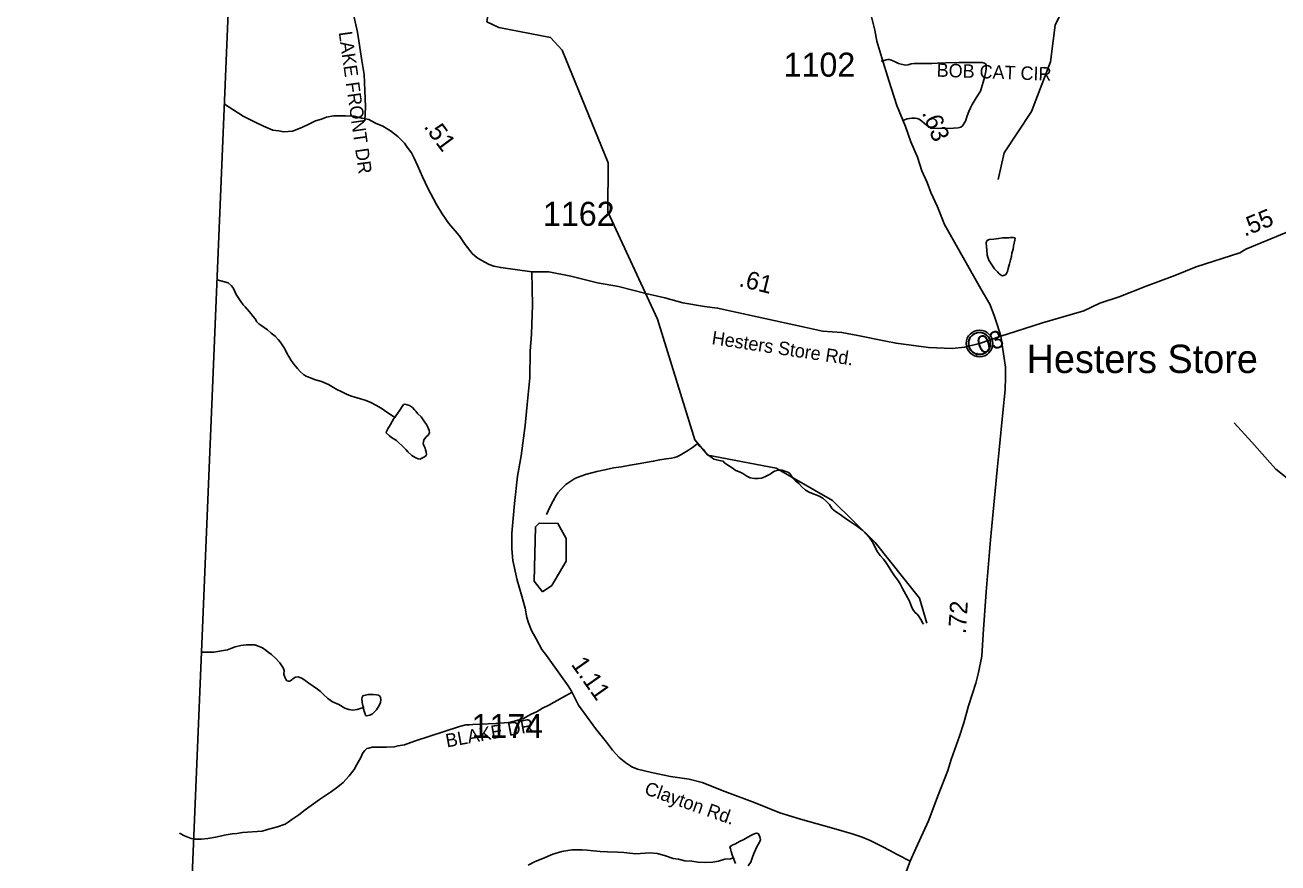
# Model space of a CAD drawing. Extents: x 1950930 to 2061844, y 904556 to 1017002.
# Drawn here: x 1954667 to 1963523, y 935352 to 941273 of the extents above; entities that cross this region are included whole.
import ezdxf

# ---------------------------------------------------------------- set-up
doc = ezdxf.new("R2010")
doc.units = 0
for name, color, linetype in [('Exist Boundary Political CountyLine', 7, 'Continuous'), ('Exist Civil Demographics Community CELL', 7, 'Continuous'), ('Exist Civil Demographics Community Label', 7, 'Continuous'), ('Exist Hydrographic Creek Single Shore', 7, 'Continuous'), ('Exist Hydrographic Misc Water Feature', 7, 'Continuous'), ('Exist Road Non-System Type 51', 7, 'Continuous'), ('Exist Road Non-System Type 51 Label', 7, 'Continuous'), ('Exist Road Primary US Structure Standard Bridge CELL', 7, 'Continuous'), ('Exist Road Secondary Type 41 Attributed', 7, 'Continuous'), ('Exist Road Secondary Type 51 Attributed', 7, 'Continuous'), ('Exist Road Secondary Type 51 Label', 7, 'Continuous'), ('Exist Road Secondary Type 51 Number Label', 7, 'Continuous')]:
    doc.layers.add(name, color=color, linetype=linetype)

msp = doc.modelspace()

# ---------------------------------------------------------------- linework, layer by layer
at = {"layer": 'Exist Boundary Political CountyLine'}
msp.add_lwpolyline([(1954666.9, 907077.7), (1956979.8, 962278.8), (1958720.5, 998184), (1959482.1, 1016167.2)], dxfattribs=at)
at = {"layer": 'Exist Civil Demographics Community CELL'}
msp.add_lwpolyline([(1961336.4, 939035.5), (1961337.4, 939041.1), (1961339.1, 939047.7), (1961342, 939054.9), (1961345, 939060.6), (1961348.3, 939066.4), (1961352.1, 939071.5), (1961356, 939075.9), (1961360.6, 939080.5), (1961366.2, 939085.1), (1961371.6, 939088.7), (1961376.5, 939091.6), (1961381.5, 939094), (1961387, 939096.3), (1961392.6, 939098.2), (1961396.9, 939099.3), (1961401.8, 939100), (1961405.9, 939100.8), (1961412.3, 939101), (1961416.7, 939100.9), (1961422.4, 939100.7), (1961427.3, 939099.9), (1961432.2, 939098.9), (1961437.2, 939097.5), (1961442.4, 939095.6), (1961449, 939092.7), (1961455.3, 939089.2), (1961460.3, 939085.6), (1961465.5, 939081.6), (1961468.8, 939078.5), (1961472.9, 939074.1), (1961476.8, 939069.4), (1961479.9, 939064.8), (1961483, 939059.8), (1961485.5, 939054.6), (1961487.5, 939049.6), (1961489.1, 939044.6), (1961490.3, 939040), (1961491.4, 939034), (1961492.1, 939029.3), (1961492.3, 939023.3), (1961492.1, 939017.5), (1961491.6, 939011.8), (1961490.6, 939006.3), (1961489, 939000.2), (1961487.1, 938994.3), (1961484.8, 938989.3), (1961481.7, 938983.3), (1961478.4, 938977.9), (1961474.9, 938973.2), (1961470.7, 938968.5), (1961465.4, 938963.5), (1961460.4, 938959.4), (1961455.4, 938956), (1961451.1, 938953.5), (1961444.2, 938950.2), (1961437.1, 938947.5), (1961431.1, 938946.1), (1961424.5, 938944.8), (1961420.1, 938944.3), (1961415.6, 938944), (1961410, 938944), (1961405.8, 938944.4), (1961400.1, 938945.2), (1961394.2, 938946.5), (1961389.6, 938947.8), (1961384.4, 938949.7), (1961379.9, 938951.6), (1961375.9, 938953.9), (1961369.1, 938958), (1961363.5, 938962.2), (1961358.6, 938966.7), (1961354.2, 938971.6), (1961351, 938975.5), (1961348, 938979.7), (1961343.9, 938986.8), (1961342.2, 938990.4), (1961340.5, 938994.4), (1961337.9, 939002.6), (1961336.4, 939009.6), (1961335.7, 939014.8), (1961335.3, 939021.1), (1961335.3, 939025.8), (1961335.8, 939032.3)], close=True, dxfattribs=at)
for centre, radius in [((1961414, 939023.1), 94.3), ((1961413.7, 939023.4), 76.7)]:
    msp.add_circle(centre, radius, dxfattribs=at)
at = {"layer": 'Exist Hydrographic Creek Single Shore'}
for points in [[(1961546.5, 940181), (1961588.4, 940370.4), (1961780.5, 940661.9), (1961915.4, 941013.6), (1961949.5, 941272.2), (1962049.5, 941480.2), (1962058.3, 941647.3), (1962000.5, 941855.4), (1962033.5, 941953.2), (1961933.5, 942063.5), (1962068.4, 942937), (1962052.4, 943019.4), (1962086.4, 943337), (1962295.4, 943628.1), (1962528.5, 943787.4), (1962595.4, 943861.6), (1962612.4, 943969.5), (1962871.4, 944134.8), (1963046.5, 944101.7), (1963260.4, 944136.7), (1963552.4, 944393.2), (1963820.4, 944465.4)], [(1961040.5, 937047.1), (1960990.4, 937222.2), (1960675.5, 937616), (1960375.5, 937914.3), (1959975.4, 938142.4), (1959492.5, 938234.4), (1959401.5, 938341.3), (1959136.3, 939193.6), (1958787.3, 939952.4), (1958788.4, 940300.3), (1958464.4, 941094.6), (1958381.3, 941185), (1958015.3, 941254.9), (1957931.4, 941296), (1957948.5, 941404), (1958082.4, 941713), (1957949.5, 942103), (1957883.5, 942110.9), (1957574.4, 941963.1), (1957474.4, 941971.7)], [(1958353, 937814.4), (1958377, 937866.4), (1958401, 937910.4), (1958421.1, 937948.3), (1958433.2, 937968.3), (1958451.2, 937988.3), (1958489.4, 938026.2), (1958531.4, 938054.1), (1958553.3, 938068.1), (1958575.5, 938078.1), (1958629.4, 938096), (1958673.5, 938107.9), (1958709.6, 938117.8), (1958765.6, 938129.7), (1958825.6, 938143.6), (1958883.5, 938151.5), (1958943.5, 938163.3), (1958999.7, 938173.3), (1959065.8, 938183.1), (1959107.6, 938191), (1959153.7, 938200.9), (1959197.6, 938208.8), (1959235.7, 938212.8), (1959257.9, 938216.8), (1959273.9, 938222.8), (1959297.9, 938234.7), (1959355.9, 938268.6), (1959384, 938288.6), (1959416, 938310.5), (1959424, 938314.5)]]:
    msp.add_lwpolyline(points, dxfattribs=at)
at = {"layer": 'Exist Hydrographic Misc Water Feature'}
for points in [[(1961551, 939764.6), (1961577, 939768.5), (1961597.1, 939768.5), (1961621.1, 939770.4), (1961633, 939772.5), (1961651.1, 939772.4), (1961661.1, 939770.4), (1961665, 939766.4), (1961662.9, 939752.4), (1961655, 939710.4), (1961650.9, 939690.3), (1961642.9, 939660.4), (1961638.8, 939638.4), (1961632.6, 939614.4), (1961630.8, 939604.4), (1961626.7, 939586.5), (1961616.6, 939552.4), (1961610.7, 939532.4), (1961604.5, 939518.4), (1961596.5, 939508.5), (1961590.6, 939504.5), (1961582.4, 939502.5), (1961574.6, 939500.5), (1961552.6, 939514.6), (1961540.5, 939528.6), (1961520.6, 939550.6), (1961500.8, 939578.6), (1961478.6, 939612.7), (1961466.7, 939646.8), (1961464.9, 939684.8), (1961463, 939706.7), (1961461, 939736.8), (1961466.9, 939750.7), (1961480.9, 939758.7), (1961514.9, 939760.7), (1961547.1, 939764.6), (1961551, 939764.6)], [(1956024.2, 939472), (1956101.7, 939450.9), (1956125.7, 939430.9), (1956139.7, 939411), (1956159.6, 939368.8), (1956167.6, 939354.9), (1956191.5, 939318.9), (1956209.4, 939294.8), (1956223.3, 939280.7), (1956253.5, 939246.7), (1956279.3, 939214.6), (1956293.2, 939196.6), (1956305.3, 939176.6), (1956319.3, 939160.5), (1956333.2, 939152.5), (1956381.2, 939118.4), (1956407.3, 939096.4), (1956434.9, 939074.3), (1956457.1, 939050.3), (1956471, 939034.3), (1956489.1, 939006.2), (1956502.8, 938984.1), (1956518.8, 938950.2), (1956530.7, 938930.1), (1956548.7, 938902.1), (1956562.7, 938884.1), (1956576.6, 938866), (1956592.6, 938845.9), (1956610.7, 938824), (1956636.5, 938801.9), (1956654.6, 938791.8), (1956690.4, 938777.8), (1956720.6, 938765.8), (1956762.6, 938753.7), (1956812.4, 938733.6), (1956836.4, 938719.4), (1956870.5, 938697.4), (1956902.5, 938683.3), (1956938.3, 938665.3), (1956966.2, 938653.2), (1956998.2, 938643.2), (1957038.2, 938631), (1957070.2, 938623), (1957110.4, 938606.9), (1957146.1, 938586.8), (1957184.2, 938564.8), (1957230.1, 938532.7), (1957272, 938506.6), (1957280, 938500.6)], [(1957280, 938500.6), (1957288, 938510.6), (1957300.3, 938528.6), (1957316.3, 938552.5), (1957332.2, 938578.5), (1957342.3, 938592.5), (1957352.3, 938594.4), (1957368.3, 938590.4), (1957384.3, 938584.4), (1957406.1, 938570.4), (1957420.2, 938554.3), (1957430.3, 938544.3), (1957444.2, 938526.3), (1957465.9, 938504.3), (1957490.1, 938470.2), (1957504.1, 938450.2), (1957513.9, 938432.1), (1957524, 938408.1), (1957525.8, 938394.1), (1957517.8, 938376.2), (1957499.8, 938360.2), (1957491.8, 938350.2), (1957487.9, 938346.2), (1957483.8, 938330.2), (1957481.7, 938316.2), (1957485.6, 938302.2), (1957495.7, 938282.1), (1957497.7, 938272.2), (1957501.6, 938258.2), (1957503.7, 938240.1), (1957501.6, 938230.2), (1957489.5, 938222.2), (1957471.5, 938212.2), (1957459.6, 938206.2), (1957445.6, 938208.2), (1957425.5, 938216.3), (1957401.6, 938232.3), (1957373.7, 938256.4), (1957357.7, 938274.3), (1957331.6, 938298.5), (1957307.8, 938322.5), (1957291.9, 938336.6), (1957279.8, 938344.6), (1957257.8, 938358.6), (1957243.9, 938370.6), (1957219.9, 938390.7), (1957221.9, 938400.7), (1957232, 938418.7), (1957249.8, 938450.7), (1957274, 938492.6), (1957280, 938500.6)], [(1963213.3, 938462.2), (1963338.4, 938326.5), (1963450.5, 938200.6), (1963508.1, 938135.6), (1963612.1, 938053.1)], [(1959424, 938314.5), (1959424, 938310.5), (1959432, 938300.4), (1959445.9, 938290.4), (1959461.9, 938274.3), (1959477.7, 938252.4), (1959499.9, 938232.3), (1959523.8, 938214.3), (1959535.7, 938206.3), (1959555.8, 938200.2), (1959585.8, 938194.2), (1959601.8, 938190.1), (1959611.6, 938180.1), (1959633.8, 938164), (1959657.7, 938148), (1959691.8, 938125.9), (1959721.5, 938113.9), (1959741.6, 938103.8), (1959769.5, 938085.7), (1959793.5, 938073.7), (1959823.6, 938067.7), (1959849.5, 938067.7), (1959873.5, 938071.6), (1959895.6, 938079.6), (1959919.6, 938091.4), (1959933.5, 938099.4), (1959951.6, 938113.4), (1959963.7, 938119.4), (1959991.8, 938127.3), (1960017.6, 938127.3), (1960037.7, 938121.3), (1960051.6, 938115.2), (1960063.7, 938111.2), (1960071.7, 938105.2), (1960081.6, 938091.1), (1960093.5, 938071.1), (1960111.5, 938055.1), (1960137.4, 938033.1), (1960157.5, 938011), (1960183.5, 937987), (1960213.4, 937970.9), (1960245.4, 937958.9), (1960279.3, 937942.8), (1960305.3, 937928.7), (1960335.2, 937904.6), (1960353.3, 937884.6), (1960371.1, 937854.5), (1960395.1, 937836.6), (1960421.2, 937818.5), (1960463, 937788.5), (1960495, 937768.3), (1960551, 937730.2), (1960588.9, 937700.2), (1960610.8, 937678.2), (1960638.7, 937648), (1960654.9, 937624), (1960670.7, 937594), (1960690.6, 937553.9), (1960712.5, 937524), (1960734.5, 937499.9), (1960754.4, 937473.8), (1960774.5, 937439.7), (1960788.4, 937415.7), (1960808.3, 937387.7), (1960820.4, 937371.7), (1960836.2, 937349.6), (1960852.2, 937323.6), (1960870.2, 937291.5), (1960894, 937249.5), (1960918, 937201.4), (1960928, 937175.4), (1960937.9, 937153.4), (1960945.9, 937135.4), (1960957.8, 937121.3), (1960973.8, 937109.3), (1960981.8, 937097.2), (1960997.8, 937071.3), (1961005.8, 937061.3), (1961011.7, 937049.3), (1961017.6, 937039.2)], [(1958324.3, 937267.3), (1958390.4, 937311.8), (1958491.5, 937483.8), (1958491.5, 937644.5), (1958433.4, 937750.9), (1958300.3, 937753.6), (1958275.3, 937727.8), (1958265.5, 937344), (1958324.3, 937267.3)], [(1957058.1, 936450.7), (1957042.1, 936444.8), (1957014, 936436.9), (1956984.1, 936432.9), (1956956, 936437), (1956928.1, 936447), (1956884.2, 936471.1), (1956840.1, 936491.1), (1956806.1, 936515.2), (1956774.3, 936545.4), (1956756.3, 936563.3), (1956734.3, 936579.4), (1956702.3, 936601.4), (1956672.4, 936623.5), (1956646.3, 936641.6), (1956622.4, 936657.6), (1956608.4, 936663.7), (1956596.3, 936667.7), (1956578.5, 936665.7), (1956560.4, 936653.7), (1956552.4, 936645.7), (1956544.4, 936639.8), (1956536.4, 936637.7), (1956526.4, 936637.7), (1956518.4, 936639.8), (1956510.4, 936649.8), (1956502.4, 936663.9), (1956496.5, 936685.8), (1956498.5, 936711.9), (1956490.5, 936731.8), (1956466.7, 936766), (1956438.6, 936795.9), (1956408.7, 936824), (1956384.7, 936842.1), (1956370.8, 936854.2), (1956344.7, 936872.2), (1956322.8, 936882.3), (1956291, 936892.3), (1956259, 936894.3), (1956230.9, 936892.4), (1956192.8, 936888.5), (1956152.8, 936878.6), (1956120.8, 936866.6), (1956098.9, 936858.7), (1956001, 936840.9), (1955914, 936840.9)], [(1957058.1, 936450.7), (1957060.1, 936440.8), (1957066.1, 936418.7), (1957072, 936406.7), (1957074.1, 936394.7), (1957081.9, 936390.7), (1957104, 936396.7), (1957122.1, 936406.6), (1957152, 936434.6), (1957170.3, 936464.6), (1957180.1, 936486.5), (1957182.2, 936506.5), (1957180.3, 936520.5), (1957178.3, 936524.5), (1957172.3, 936532.5), (1957166.4, 936536.6), (1957150.4, 936540.6), (1957128.2, 936542.7), (1957116.3, 936542.7), (1957094.4, 936542.7), (1957062.2, 936534.8), (1957052.4, 936530.8), (1957048.3, 936510.8), (1957050.1, 936486.8), (1957054.2, 936464.8), (1957058.1, 936450.7)], [(1959674.4, 935387.6), (1959668.4, 935403.6), (1959658.4, 935433.7), (1959652.4, 935451.6), (1959648.5, 935465.6), (1959664.5, 935477.5), (1959688.5, 935487.6), (1959716.6, 935503.5), (1959742.6, 935515.5), (1959764.8, 935527.4), (1959792.7, 935543.4), (1959810.7, 935553.3), (1959828.8, 935561.3), (1959838.6, 935563.3), (1959850.7, 935557.3), (1959860.7, 935537.2), (1959864.6, 935515.3), (1959856.6, 935495.2), (1959842.5, 935471.3), (1959830.4, 935445.2), (1959820.4, 935423.3), (1959810.3, 935399.3), (1959802.3, 935371.3), (1959800.3, 935367.3), (1959798.4, 935361.4), (1959778.1, 935331.4)], [(1959674.4, 935387.6), (1959654.3, 935381.7), (1959614.3, 935379.7), (1959568.3, 935365.8), (1959528.2, 935357.9), (1959470.1, 935355.9), (1959424.2, 935358.1), (1959380.3, 935364.1), (1959330.3, 935368.2), (1959286.4, 935378.3), (1959248.3, 935384.3), (1959194.3, 935402.5), (1959138.3, 935418.7), (1959082.4, 935424.7), (1958984.4, 935416.8), (1958900.3, 935427.1), (1958858.2, 935429.1), (1958784.2, 935431.3), (1958732.3, 935433.4), (1958686.2, 935437.6), (1958640.3, 935443.6), (1958604.4, 935445.7), (1958576.3, 935445.7), (1958532.2, 935443.8), (1958462.3, 935431.9), (1958398.1, 935414.1), (1958326.1, 935384.2), (1958272.2, 935362.3), (1958224, 935336.4)], [(1959688.3, 935347.5), (1959680.3, 935371.6), (1959674.4, 935387.6)]]:
    msp.add_lwpolyline(points, dxfattribs=at)
at = {"layer": 'Exist Road Non-System Type 51'}
for points in [[(1957067.5, 940596.1), (1957072.6, 940694.9), (1957069.8, 940809.6), (1957062.9, 940923.4), (1957048.5, 941023), (1957017, 941222), (1956966, 941452.5), (1956921.5, 941690.8), (1956884.8, 941893.8), (1956867.8, 941933.1), (1956831.1, 941986.8), (1956782.6, 942041.8), (1956697.5, 942136.1), (1956692.2, 942168.8), (1956692.2, 942217.2), (1956689.4, 942240.3)], [(1960719.4, 941017.1), (1960739.1, 941022.8), (1960754.9, 941028.1), (1960767.1, 941030.6), (1960776, 941028.7), (1960792.6, 941023.7), (1960822.2, 941010.4), (1960841.1, 941001.3), (1960858.8, 940996.6), (1960891.1, 940988.4), (1960909.4, 940991.3), (1960931, 940999.2), (1960951.1, 941001.7), (1960973.4, 941002.2), (1961009.8, 941001.2), (1961075.6, 941001.2), (1961114.5, 941003.6), (1961176, 941005.6), (1961267, 941007.6), (1961349.1, 941007.6), (1961372.8, 941008.1), (1961409.1, 941008.1), (1961433.2, 941007.1), (1961448.5, 941004.1), (1961455.9, 940999.2), (1961461.2, 940990.9), (1961461.8, 940981), (1961461.8, 940966.2), (1961457.4, 940944.1), (1961448, 940902.3), (1961439.1, 940869.8), (1961432.8, 940844.8), (1961421.5, 940805.4), (1961391, 940759.6), (1961361.5, 940711.4), (1961350.1, 940687.3), (1961338.8, 940661.2), (1961326, 940630.8), (1961313.8, 940594.9), (1961294.5, 940559.9), (1961281.2, 940551.6), (1961261.6, 940546.2), (1961229.6, 940544.7), (1961123.4, 940542.7), (1961086.5, 940543.2), (1961070.2, 940545.2), (1961052, 940555), (1961038.8, 940565.3), (1961005.8, 940594.9), (1960988.1, 940608.6), (1960973.8, 940613.6), (1960958.5, 940615.5), (1960935.9, 940615.5), (1960903, 940609.6), (1960867.2, 940596.1)], [(1958534.6, 936558.8), (1958466.2, 936521.7), (1958368.8, 936467.5), (1958324.2, 936445.8), (1958286.9, 936421.8), (1958239.9, 936401.3), (1958190.5, 936373.6), (1958143.6, 936359.1), (1958118.2, 936350.7), (1958084.6, 936344.7), (1958054.5, 936341.1), (1957994.2, 936337.4), (1957831.8, 936330.9), (1957808.9, 936328.4), (1957783.5, 936327.2), (1957737.8, 936316.4), (1957419.9, 936212.8), (1957350, 936186.9), (1957304.2, 936179.8), (1957276.6, 936172.5), (1957222.4, 936171.3), (1957155, 936170.1), (1957121.2, 936169.5), (1957097.1, 936163.4), (1957082.8, 936159.9), (1957068.2, 936146.6), (1957055, 936130.9), (1957039.4, 936097.2), (1957011.6, 936047.9), (1956992.4, 936011.8), (1956957.5, 935967.2), (1956934.6, 935941.9), (1956916.5, 935921.4), (1956878, 935890.1), (1956832.2, 935856.4), (1956749.1, 935800.4), (1956648, 935728.2), (1956601, 935692.1), (1956551.8, 935658.3), (1956527.6, 935641.4), (1956504.8, 935627), (1956451.8, 935606.6), (1956380.8, 935588.5), (1956343.4, 935576.4), (1956204.9, 935567.4), (1956164, 935561.4), (1956130.2, 935557.8), (1956089.2, 935551.8), (1956013.4, 935534.9), (1955958, 935525.2), (1955913.5, 935519.2), (1955866.5, 935519.8), (1955841.2, 935524.7), (1955794.2, 935542.8), (1955758.1, 935562)]]:
    msp.add_lwpolyline(points, dxfattribs=at)
at = {"layer": 'Exist Road Secondary Type 41 Attributed'}
msp.add_lwpolyline([(1956076.2, 940713.1), (1956209, 940628.4), (1956287.8, 940589), (1956351.3, 940558.4), (1956419.1, 940529.9), (1956458.5, 940524.8), (1956472.5, 940522.7), (1956482.2, 940521), (1956496.6, 940518.6), (1956556.5, 940522.2), (1956622.7, 940549.8), (1956673, 940573.6), (1956721.1, 940595.2), (1956761.2, 940609), (1956797.3, 940622.6), (1956847.3, 940630.4), (1956931.3, 940631.9), (1956993.3, 940629.6), (1957045.2, 940615.1), (1957049.2, 940615.2), (1957097.2, 940604.8), (1957145.1, 940580.7), (1957196.9, 940558.4), (1957250.8, 940526.1), (1957302.6, 940485.8), (1957348.3, 940439.4), (1957368.1, 940409.4), (1957397.9, 940369.2), (1957417.7, 940332.9), (1957443.4, 940276.8), (1957476.8, 940200.7), (1957514.4, 940120.5), (1957575.6, 940004.2), (1957615.3, 939939.9), (1957662.9, 939871.7), (1957736.3, 939785.2), (1957778, 939721.1), (1957827.6, 939658.9), (1957863.3, 939628.5), (1957917.1, 939598.2), (1957947.2, 939580), (1957981, 939569.9), (1958029, 939559.5), (1958250.3, 939529.5)], dxfattribs=at)
at = {"layer": 'Exist Road Secondary Type 51 Attributed'}
for points in [[(1961564.4, 939074.1), (1961539.3, 939157.7), (1961518.1, 939221.5), (1961486.2, 939299.5), (1961422.4, 939409.4), (1961319.6, 939593.7), (1961167.3, 939864.1), (1961116.1, 939988.4), (1961068.5, 940090.6), (1961043, 940160.8), (1961005.5, 940243), (1960974.2, 940339.1), (1960928.8, 940447.2), (1960889.5, 940555.5), (1960830.3, 940703.8), (1960771.5, 940880), (1960722.4, 941040.3), (1960687.2, 941158.5), (1960673.6, 941236.4), (1960646.4, 941350.6)], [(1961564.4, 939074.1), (1961668.5, 939107.5), (1961859, 939168.2), (1962151.5, 939254.4), (1962263.8, 939307.7), (1962400.2, 939352.9), (1962592.8, 939427.6), (1962795.2, 939502.5), (1962945.5, 939563.6), (1963254.9, 939663.7), (1963297.1, 939689.6), (1963581.7, 939807.6), (1963618.8, 939828.4), (1963637.7, 939841), (1963693.6, 939882.3), (1963984.2, 940077.4), (1964134.4, 940194.8), (1964197.3, 940237.9)], [(1960924.1, 935365.2), (1960831.6, 935411.9), (1960780.2, 935440.3), (1960730.3, 935466.5), (1960640.6, 935511), (1960584.7, 935535.4), (1960512.9, 935557.8), (1960385, 935594.7), (1960149.3, 935662), (1960001.6, 935706.8), (1959828, 935776), (1959612.6, 935857.3), (1959453.3, 935919.6), (1959361.6, 935943.7), (1959229.2, 935963.3), (1959095.3, 935991.9), (1958996.1, 936016), (1958956.9, 936031), (1958912.6, 936058.9), (1958867.4, 936098), (1958819.3, 936149.2), (1958777.2, 936206.4), (1958698.4, 936303.3), (1958579.9, 936466.5), (1958528.6, 936565.7), (1958504.8, 936603.8), (1958353, 936819.2), (1958320.7, 936859.5), (1958279.3, 936935.8), (1958247.3, 936995.7), (1958224.8, 937049.9), (1958214.2, 937086), (1958202.2, 937153.4), (1958178.8, 937237.5), (1958144.3, 937350.3), (1958115.7, 937490.3), (1958107.4, 937572.3), (1958108.9, 937682.2), (1958118, 937786.1), (1958127.7, 937892.3), (1958148.8, 938085), (1958174.4, 938229.5), (1958202.2, 938442.5), (1958217.2, 938591.6), (1958235.3, 938779.8), (1958237.5, 938968.7), (1958246.6, 939089.2), (1958253.3, 939293.2), (1958250.3, 939529.5)], [(1958250.3, 939529.5), (1958368.9, 939529.5), (1958524.7, 939498.6), (1958714.4, 939451.3), (1958862.3, 939424.5), (1959054.1, 939375.3), (1959190.3, 939345.8), (1959317.1, 939309.6), (1959469.6, 939284.9), (1959561.6, 939273.3), (1960177.4, 939137.4), (1960304.2, 939110.2), (1960440.1, 939101.2), (1960552.5, 939080.3), (1960752.4, 939039), (1960824.3, 939024.7), (1961054.2, 938995.1), (1961220.3, 938988.1), (1961308.2, 938995.7), (1961414, 939023.1), (1961564.4, 939074.1)], [(1960924.1, 935365.2), (1960964.3, 935455.1), (1961053.6, 935650.5), (1961120.7, 935830), (1961189.8, 936005.5), (1961214.2, 936083.4), (1961271.2, 936248.9), (1961301.9, 936342.7), (1961336.6, 936462.4), (1961387.5, 936622), (1961406.1, 936697.9), (1961428.9, 936813.8), (1961439.7, 936967.7), (1961459.7, 937267.4), (1961491.9, 937635), (1961538.9, 938130.6), (1961551.8, 938272.4), (1961577.5, 938536.2), (1961594.5, 938694.1), (1961597, 938785.9), (1961597.5, 938855.9), (1961564.4, 939074.1)], [(1960506.7, 933335), (1960509.7, 933438.9), (1960514.2, 933538.3), (1960521.7, 933691.1), (1960517.2, 933907.9), (1960521.7, 934044.9), (1960524.7, 934106.6), (1960532.3, 934172.9), (1960544.3, 934245.1), (1960567.3, 934323.9), (1960589.9, 934423.8), (1960609.7, 934533.4), (1960645.7, 934648.1), (1960706.9, 934837.7), (1960787.6, 935004.4), (1960924.1, 935365.2)]]:
    msp.add_lwpolyline(points, dxfattribs=at)

# ---------------------------------------------------------------- texts
at = {"layer": 'Exist Civil Demographics Community Label'}
msp.add_text('Hesters Store', height=200, dxfattribs=at).set_placement((1961746.4, 938814.2))
at = {"layer": 'Exist Road Non-System Type 51 Label'}
for s, rotation, p in [('  LAKE FRONT DR', 278.05083, (1956873.6, 941291.8)), ('  BOB CAT CIR', 357.95193, (1961038.9, 940910.8)), ('  BLAKE DR', 10.44461, (1957579.4, 936154.8))]:
    msp.add_text(s, height=95, rotation=rotation, dxfattribs=at).set_placement(p)
at = {"layer": 'Exist Road Primary US Structure Standard Bridge CELL'}
for s, rotation, p in [('.63', 291.76119, (1961004.8, 940653.6)), ('.51', 306.54909, (1957481.4, 940554.7)), ('.55', 22.12263, (1963288.1, 939776.4)), ('.61', 346.03406, (1959707.2, 939428.6)), ('.03', 18.73177, (1961376.6, 938930.4)), ('.72', 86.18214, (1961316.2, 936967.6)), ('1.11', 305.17738, (1958522.7, 936755.4))]:
    msp.add_text(s, height=125, rotation=rotation, dxfattribs=at).set_placement(p)
at = {"layer": 'Exist Road Secondary Type 51 Label'}
for s, rotation, p in [('Hesters Store Rd.', 351.37798, (1959516.5, 939018.2)), ('Clayton Rd.', 340.54648, (1959038.4, 935840.8))]:
    msp.add_text(s, height=95, rotation=rotation, dxfattribs=at).set_placement(p)
at = {"layer": 'Exist Road Secondary Type 51 Number Label'}
for s, p in [('1102', (1960029.5, 940908)), ('1162', (1958328.2, 939854)), ('1174', (1957822.9, 936234.5))]:
    msp.add_text(s, height=170, dxfattribs=at).set_placement(p)

doc.saveas('drawing.dxf')
